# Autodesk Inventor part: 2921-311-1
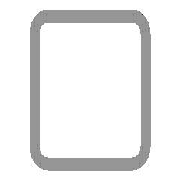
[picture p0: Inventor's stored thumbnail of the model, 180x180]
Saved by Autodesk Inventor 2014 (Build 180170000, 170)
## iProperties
IsCustomPart: 1
Company: NHTSA/VRTC
Created: 2012-02
Part Number: 2921-311-1
Material: Steel, Mild
Description: BENCH FRAME TUBE #1
Document SubType Name: Modeling
Standard: AISC
Designer: Mike Vanvoorhis
Standards Organization: ANSI
Language: en-US
Size Designation: 1-1/2x1-1/2x1/8 - 29.2
Categories: <MemberInstance><Categories><Category DisplayName="Structural Shapes" InternalName="089c4875-fa83-4c05-b084-43b9cc11f5ed" Mnemonic="GRDR"><CategoryParameter Dis
Stock Number: T.S. 1 1/2 x1 1/2 x 1/8 x741.7mm (29.20")
Density: 1 g/cm^3
Project: CHILD SIDE IMPACT SLED
Appearance: Steel
G_L: 29.200 in
DESIGN DATE: 2012-11-05
Author: Dave Walker
Title: Bench Frame Tube #1
Subject: Child Side Impact Sled
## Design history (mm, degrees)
node "Start plane"
node "End plane"
sketch "Sketch"
  geometry: L1 (-19.05, -12.7)-(-19.05, 12.7); L2 (-12.7, 19.05)-(12.7, 19.05); L3 (19.05, 12.7)-(19.05, -12.7); L4 (12.7, -19.05)-(-12.7, -19.05); L5 (-12.7, 15.875)-(12.7, 15.875); L6 (15.875, 12.7)-(15.875, -12.7); L7 (12.7, -15.875)-(-12.7, -15.875); L8 (-15.875, -12.7)-(-15.875, 12.7); L9 (0, 36.948)-(0, -36.948) reference; L10 (-23.079, 0)-(23.079, 0) reference; A1 r 6.35 centre (-12.7, -12.7) between (-19.05, -12.7) and (-12.7, -19.05); A2 r 6.35 centre (-12.7, 12.7) between (-12.7, 19.05) and (-19.05, 12.7); A3 r 6.35 centre (12.7, 12.7) between (19.05, 12.7) and (12.7, 19.05); A4 r 6.35 centre (12.7, -12.7) between (12.7, -19.05) and (19.05, -12.7); A5 r 3.175 centre (-12.7, 12.7) between (-12.7, 15.875) and (-15.875, 12.7); A6 r 3.175 centre (12.7, 12.7) between (15.875, 12.7) and (12.7, 15.875); A7 r 3.175 centre (12.7, -12.7) between (12.7, -15.875) and (15.875, -12.7); A8 r 3.175 centre (-12.7, -12.7) between (-15.875, -12.7) and (-12.7, -15.875)
  constraints: 16 end point, 16 point on circle, 8 centre point, 8 tangent, 4 parallel, 3 equal radius, 2 perpendicular, 7 other
  dimensions: "d10" = 38.1 distance between parallel lines of L2 L4 (= G_H); "d11" = 38.1 distance between parallel lines of L1 L3 (= G_W); "d12" = 3.175 distance between parallel lines of L3 L6 (= G_T); "d15" = 19.05 distance between parallel lines of L2 L10 (= 0.5 x d10); "d16" = 19.05 distance between parallel lines of L9 L3 (= 0.5 x d11); "d17" = 6.35 radius of A1 (= G_IR)
extrude "Body" new body sketch "Sketch" stored distance "d3" = 741.68 (= G_L); taper "d4" = 0 deg
node "Driven Length"
  sketch "Sketch3"
    geometry: L1 (0, 0)-(10, 0) reference
    constraints: 2 end point, 1 horizontal
  workplane "Work Plane3"
  sketch "Sketch4"
    geometry: L1 (-2, 0)-(12, 0) reference; L2 (-2, 741.68)-(12, 741.68) reference
    dimensions: "d19" = 741.68 distance between parallel lines of L1 L2 (derived)
body "Solid1"
other parameters: "G_W" = 38.1 [user parameter; used in 1 equation term], "G_H" = 38.1 [user parameter; used in 1 equation term], "G_T" = 3.175 [user parameter; used in 1 equation term], "G_IR" = 6.35 [user parameter; used in 1 equation term], "G_L" = 741.68 (= d19) [user parameter; used in 1 equation term], "G_OFFSET_START" = 0 [user parameter; used in 1 equation term], "G_OFFSET_END" = 0 [user parameter; used in 1 equation term], "d13" = 0 (computed from G_OFFSET_START), "d14" = 741.68 (= G_OFFSET_END + B_L), "B_L" = 741.68 [user parameter; used in 1 equation term], "d18" = 90 deg
